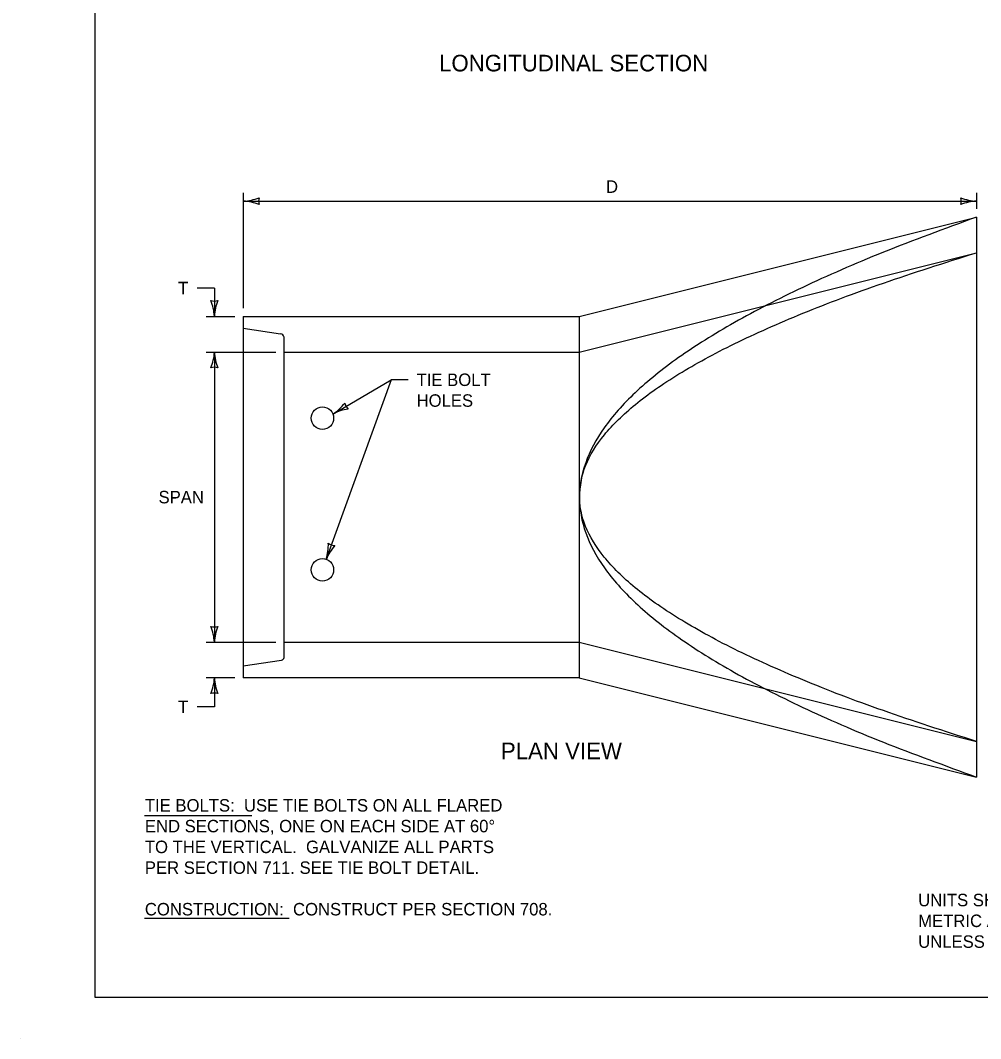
# Model space of a CAD drawing. Extents: x 49991.4 to 50021, y 49987.6 to 50011.4.
# Drawn here: x 49999.977 to 50004.599, y 49999.862 to 50004.765 of the extents above; entities that cross this region are included whole.
import ezdxf

# ---------------------------------------------------------------- set-up
doc = ezdxf.new("R2010")
doc.units = 0
for name, color, linetype in [('Level 1', 7, 'Continuous'), ('Level 2', 7, 'Continuous'), ('Level 3', 7, 'Continuous'), ('Level 4', 7, 'Continuous')]:
    doc.layers.add(name, color=color, linetype=linetype)

msp = doc.modelspace()

# ---------------------------------------------------------------- linework, layer by layer
at = {"layer": 'Level 1'}
for p, q in [((50002.6674, 50003.3397), (50004.5792, 50003.8176)), ((50004.5792, 50003.8176), (50004.5792, 50001.1217)), ((50001.0498, 50003.3397), (50001.0498, 50001.5997)), ((50001.0498, 50003.3397), (50002.6674, 50003.3397)), ((50001.0498, 50003.3397), (50002.6674, 50003.3397)), ((50002.6674, 50003.3397), (50002.6674, 50001.5997)), ((50002.6674, 50001.5997), (50001.0498, 50001.5997)), ((50002.6674, 50001.5997), (50004.5792, 50001.1217)), ((49999.9766, 49999.8624), (49999.9766, 49999.8624))]:
    msp.add_line(p, q, dxfattribs=at)
msp.add_lwpolyline([(50008.6146, 50011.2628), (50000.3356, 50011.2628), (50000.3356, 50000.0624), (50008.6146, 50000.0624)], close=True, dxfattribs=at)
for centre in [(50001.4305, 50002.8495), (50001.4305, 50002.1194)]:
    msp.add_circle(centre, 0.0541, dxfattribs=at)
for points in [[(50004.5792, 50003.8176), (50000.7573, 50002.4637), (50004.5792, 50001.1217)], [(50004.5792, 50001.2929), (50000.7571, 50002.4802), (50004.5792, 50003.6459)]]:
    msp.add_open_spline(points, degree=2, dxfattribs=at)
at = {"layer": 'Level 2'}
for p, q in [((50000.5737, 50000.9367), (50001.0901, 50000.9367)), ((50000.5747, 50000.4428), (50001.2699, 50000.4428))]:
    msp.add_line(p, q, dxfattribs=at)
at = {"layer": 'Level 3'}
for p, q in [((50001.0498, 50003.9342), (50001.0498, 50003.3797)), ((50004.5792, 50003.9342), (50004.5792, 50003.8576)), ((50001.0498, 50003.8942), (50004.5792, 50003.8942)), ((50000.9104, 50003.4759), (50000.8277, 50003.4759)), ((50000.9104, 50003.4759), (50000.9104, 50003.3397)), ((50000.8704, 50003.3397), (50001.0098, 50003.3397)), ((50000.8704, 50003.1679), (50001.2057, 50003.1679)), ((50000.9104, 50003.1679), (50000.9104, 50001.7709)), ((50001.7613, 50003.0344), (50001.4489, 50002.1703)), ((50001.4809, 50002.8693), (50001.7613, 50003.0344)), ((50001.844, 50003.0344), (50001.7613, 50003.0344)), ((50000.8704, 50001.7709), (50001.2057, 50001.7709)), ((50001.0098, 50001.5997), (50000.8704, 50001.5997)), ((50000.9104, 50001.5997), (50000.9104, 50001.4594)), ((50000.9104, 50001.4594), (50000.8277, 50001.4594))]:
    msp.add_line(p, q, dxfattribs=at)
for centre, radius, start, end in [((50001.0383, 50004.1269), 0.233, 272.8273, 292.0772), ((50001.0407, 50003.6721), 0.2223, 67.456, 87.6395), ((50001.178, 50003.8942), 0.0548, 162.1388, 197.8612), ((50004.5884, 50004.1164), 0.2223, 247.456, 267.6395), ((50004.451, 50003.8942), 0.0548, 342.1388, 17.8612), ((50004.5907, 50003.6615), 0.233, 92.8273, 112.0772), ((50000.9104, 50003.4679), 0.0548, 252.1388, 287.8612), ((50000.6777, 50003.3282), 0.233, 2.8273, 22.0772), ((50001.1326, 50003.3306), 0.2223, 157.456, 177.6395), ((50000.6883, 50003.1771), 0.2223, 337.456, 357.6395), ((50001.1431, 50003.1794), 0.233, 182.8273, 202.0772), ((50000.9104, 50003.0397), 0.0548, 72.1388, 107.8612), ((50001.3529, 50003.064), 0.233, 303.317, 322.5668), ((50001.5857, 50002.6732), 0.2223, 97.9457, 118.1292), ((50001.5914, 50002.9343), 0.0548, 192.6285, 228.3508), ((50001.2262, 50002.2386), 0.233, 342.9508, 2.2006), ((50001.6547, 50002.0862), 0.2223, 137.5795, 157.763), ((50001.4925, 50002.2909), 0.0548, 232.2623, 267.9846), ((50000.9104, 50001.8991), 0.0548, 252.1388, 287.8612), ((50000.6777, 50001.7594), 0.233, 2.8273, 22.0772), ((50001.1326, 50001.7618), 0.2223, 157.456, 177.6395), ((50000.6883, 50001.6089), 0.2223, 337.456, 357.6395), ((50001.1431, 50001.6112), 0.233, 182.8273, 202.0772), ((50000.9104, 50001.4715), 0.0548, 72.1388, 107.8612)]:
    msp.add_arc(centre, radius, start, end, dxfattribs=at)
at = {"layer": 'Level 4'}
for p, q in [((50002.6674, 50003.1679), (50004.5792, 50003.6459)), ((50001.0498, 50003.2826), (50001.2286, 50003.2562)), ((50001.2457, 50003.2392), (50001.2457, 50001.6972)), ((50001.2457, 50003.1679), (50002.6674, 50003.1679)), ((50001.2457, 50001.7709), (50002.6674, 50001.7709)), ((50002.6674, 50001.7709), (50004.5792, 50001.2929)), ((50001.0498, 50001.6567), (50001.2339, 50001.6843))]:
    msp.add_line(p, q, dxfattribs=at)
for centre, radius, start, end in [((50001.2249, 50003.2353), 0.0212, 10.5432, 79.8685), ((50001.2297, 50001.7), 0.0163, 285.0552, 350.1332)]:
    msp.add_arc(centre, radius, start, end, dxfattribs=at)

# ---------------------------------------------------------------- texts
at = {"layer": 'Level 2'}
for s, height, p in [('LONGITUDINAL SECTION', 0.08, (50001.9921, 50004.5189)), ('D', 0.06, (50002.7958, 50003.9342)), ('T', 0.06, (50000.7357, 50003.4459)), ('TIE BOLT', 0.06, (50001.884, 50003.0044)), ('HOLES', 0.06, (50001.884, 50002.9044)), ('SPAN', 0.06, (50000.6417, 50002.4394)), ('T', 0.06, (50000.7357, 50001.4294)), ('PLAN VIEW', 0.08, (50002.2898, 50001.2077)), ('TIE BOLTS:  USE TIE BOLTS ON ALL FLARED', 0.06, (50000.5759, 50000.9556)), ('END SECTIONS, ONE ON EACH SIDE AT 60°', 0.06, (50000.5759, 50000.8556)), ('TO THE VERTICAL.  GALVANIZE ALL PARTS', 0.06, (50000.5759, 50000.7556)), ('PER SECTION 711. SEE TIE BOLT DETAIL.', 0.06, (50000.5759, 50000.6556)), ('UNITS SHOWN IN BRACKETS [] ARE ', 0.06, (50004.2986, 50000.4996)), ('CONSTRUCTION:  CONSTRUCT PER SECTION 708.', 0.06, (50000.5759, 50000.4556)), ('METRIC AND ARE IN MILLIMETERS (mm) ', 0.06, (50004.2986, 50000.3996)), ('UNLESS OTHER UNITS ARE SHOWN.', 0.06, (50004.2986, 50000.2996))]:
    msp.add_text(s, height=height, dxfattribs=at).set_placement(p)

doc.saveas('drawing.dxf')
